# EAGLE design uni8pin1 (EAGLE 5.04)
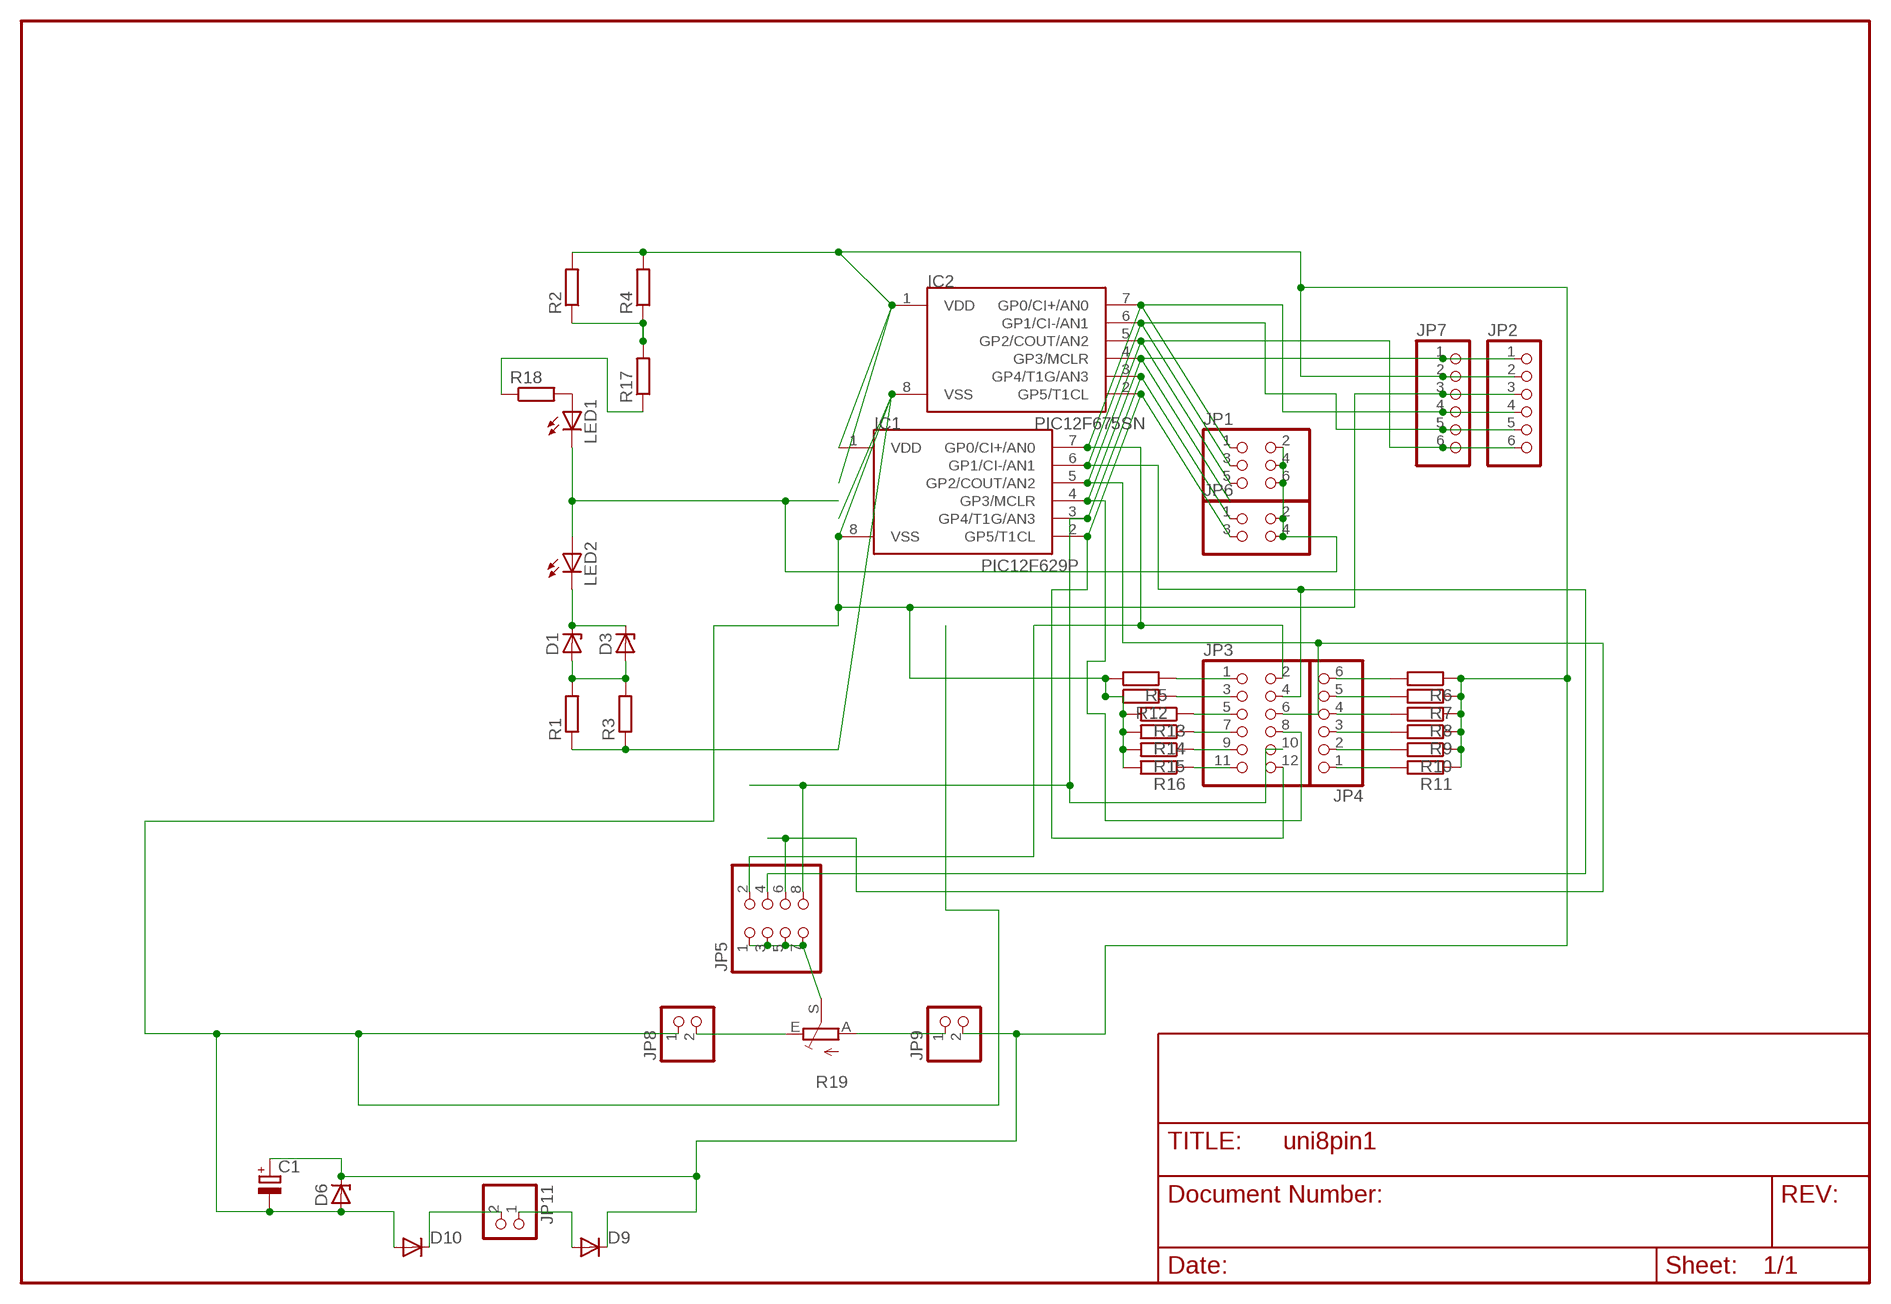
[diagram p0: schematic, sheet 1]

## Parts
C1  CPOL-EU5-13  [2,5-5-FLAT]
D1  ZENER-DIODESOT23  [SOT23]
D3  ZENER-DIODEZD-2.5  [ZDIO-2.5]
D6  ZENER-DIODEZD-2.5  [ZDIO-2.5]
D9  DIODE-D-5  [D-5]
D10  DIODE-D-5  [D-5]
IC1  PIC12F629P  [DIL8]
IC2  PIC12F675SN  [SO-08]
JP1  PINHD-2X3  [2X03]
JP2  PINHD-1X6  [1X06]
JP3  PINHD-2X6  [2X06]
JP4  PINHD-1X6  [1X06]
JP5  PINHD-2X4  [2X04]
JP6  PINHD-2X2  [2X02]
JP7  PINHD-1X6  [1X06]
JP8  PINHD-1X2  [1X02]
JP9  PINHD-1X2  [1X02]
JP11  PINHD-1X2  [1X02]
LED1  LED5MM  [LED5MM]
LED2  LED5MM  [LED5MM]
R1  R-EU_0204/2V  [0204V]
R2  R-EU_0204/2V  [0204V]
R3  R-EU_R1206  [R1206]
R4  R-EU_R1206  [R1206]
R5  R-EU_R1206  [R1206]
R6  R-EU_R1206  [R1206]
R7  R-EU_R1206  [R1206]
R8  R-EU_R1206  [R1206]
R9  R-EU_R1206  [R1206]
R10  R-EU_R1206  [R1206]
R11  R-EU_R1206  [R1206]
R12  R-EU_R1206  [R1206]
R13  R-EU_R1206  [R1206]
R14  R-EU_R1206  [R1206]
R15  R-EU_R1206  [R1206]
R16  R-EU_R1206  [R1206]
R17  R-EU_R0805  [R0805]
R18  R-EU_R0805  [R0805]
R19  TRIM_EU-CA6V  [CA6V]

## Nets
N$1: IC1.3(GP4/T1G/AN3) IC2.3(GP4/T1G/AN3) JP3.10 JP5.8 JP6.1
N$2: D1.3(C) D3.C LED2.K(C)
N$3: D1.1(A) D3.A R1.2 R3.2
N$4: JP1.2 JP1.4 JP1.6 JP6.2 JP6.4 LED1.K(C) LED2.A
N$5: C1.- D6.A D10.A IC1.8(VSS) IC2.8(VSS) JP2.3 JP7.3 JP8.1 R1.1 R3.1 R5.2 R12.2 R13.2 R14.2 R15.2 R16.2
N$6: C1.+ D6.C D9.C IC1.1(VDD) IC2.1(VDD) JP2.2 JP7.2 JP9.2 R2.2 R4.2 R6.1 R7.1 R8.1 R9.1 R10.1 R11.1
N$7: R2.1 R4.1 R17.2
N$8: R17.1 R18.1
N$9: IC1.2(GP5/T1CL) IC2.2(GP5/T1CL) JP3.12 JP6.3
N$10: LED1.A R18.2
N$11: IC1.4(GP3/MCLR) IC2.4(GP3/MCLR) JP2.1 JP3.8 JP7.1
N$12: IC1.5(GP2/COUT/AN2) IC2.5(GP2/COUT/AN2) JP1.5 JP2.6 JP3.6 JP5.6 JP7.6
N$13: IC1.6(GP1/CI-/AN1) IC2.6(GP1/CI-/AN1) JP1.3 JP2.5 JP3.4 JP5.4 JP7.5
N$14: IC1.7(GP0/CI+/AN0) IC2.7(GP0/CI+/AN0) JP1.1 JP2.4 JP3.2 JP5.2 JP7.4
N$15: JP4.6 R6.2
N$16: JP5.1 JP5.3 JP5.5 JP5.7 R19.S
N$18: JP3.1 R5.1
N$21: JP3.3 R12.1
N$22: JP3.5 R13.1
N$23: JP3.7 R14.1
N$24: JP3.9 R15.1
N$25: JP3.11 R16.1
N$26: JP4.5 R7.2
N$27: JP4.4 R8.2
N$28: JP4.3 R9.2
N$29: JP4.2 R10.2
N$30: JP4.1 R11.2
N$31: JP9.1 R19.A
N$32: JP8.2 R19.E
N$34: D10.C JP11.2
N$35: D9.A JP11.1

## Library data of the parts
C1 = rcl-2:CPOL-EU: POLARIZED CAPACITOR, European symbol
D1 D3 D6 = diode-1:ZENER-DIODE: Z-Diode
D9 D10 = diode-1:DIODE-: DIODE
IC1 IC2 = microchip-5:PIC12F6*: uPC nW 1k Program Flash memory 2x Timer Comparator 10b A/D converter/ 4xIN
JP1 = pinhead(2):PINHD-2X3: PIN HEADER
JP2 JP7 = pinhead:PINHD-1X6: PIN HEADER
JP3 = pinhead(2):PINHD-2X6: PIN HEADER
JP4 = pinhead(2):PINHD-1X6: PIN HEADER
JP5 = pinhead(2):PINHD-2X4: PIN HEADER
JP6 = pinhead(2):PINHD-2X2: PIN HEADER
JP8 JP9 JP11 = pinhead(2):PINHD-1X2: PIN HEADER
LED1 LED2 = led:LED: LED
R1-R18 = rcl-2:R-EU_: RESISTOR, European symbol
R19 = pot:TRIM_EU-: POTENTIOMETER

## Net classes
0 default: width 0.3 mm, drill 0.6 mm, clearance 0.2 mm
1 power: width 0.4 mm, drill 0.6 mm, clearance 0.2 mm

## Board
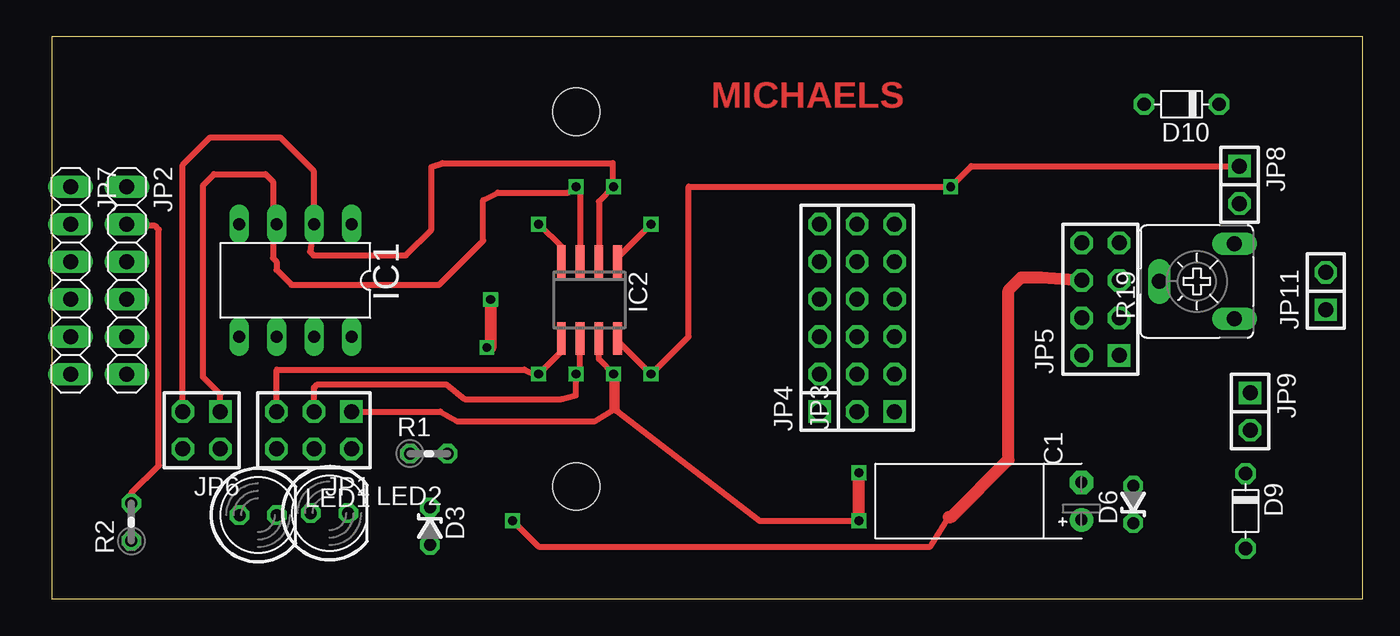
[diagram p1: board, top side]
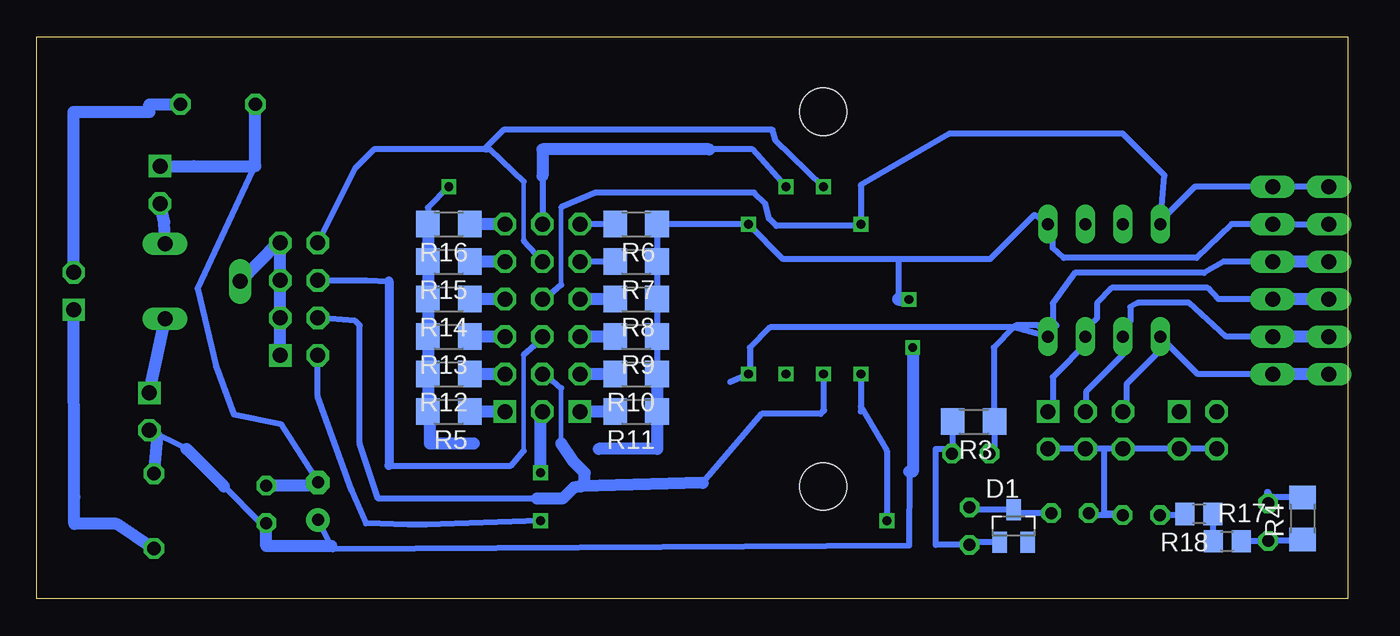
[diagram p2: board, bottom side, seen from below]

Size 88.9 x 38.1 mm. Coordinates in mm from the lower left corner, seen from the top.
Outline: 0,0 88.9,0 88.9,38.1 0,38.1 0,0
Copper layers (1*16): Top 0.035mm / dielectric 1.5mm / Bottom 0.035mm
Design rules "default": minimum track width 10mil, minimum drill 24mil, track to track 8mil, track to pad 8mil, pad to pad 8mil, via to via 8mil, smd to smd 8mil, copper to edge 40mil, drill to drill 8mil, minimum pad ring 10mil, minimum via ring 8mil, stop-mask expansion 4mil, vias tented up to drill 0mil, thermal gap 10mil
Holes 3.2 mm at 35.56,33.02 35.56,7.62

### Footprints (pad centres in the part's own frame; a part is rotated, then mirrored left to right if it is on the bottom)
2,5-5-FLAT = drill 0.813 pad 1.6 round: + -1.27,0 | drill 0.813 pad 1.6 octagon: - 1.27,0
SOT23 = smd 1 x 1.4: 1 -0.95,-1.1; 2 0.95,-1.1; 3 0,1.1
ZDIO-2.5 = drill 0.813 octagon: A 1.27,0; C -1.27,0
D-5 = drill 0.9 octagon: A 2.54,0; C -2.54,0
DIL8 = drill 0.813 long: 1 -3.81,-3.81; 2 -1.27,-3.81; 3 1.27,-3.81; 4 3.81,-3.81; 5 3.81,3.81; 6 1.27,3.81; 7 -1.27,3.81; 8 -3.81,3.81
SO-08 = smd 0.6 x 2.2: 1 -1.905,-2.6; 2 -0.635,-2.6; 3 0.635,-2.6; 4 1.905,-2.6; 5 1.905,2.6; 6 0.635,2.6; 7 -0.635,2.6; 8 -1.905,2.6
2X03 = drill 1.016 square: 1 -2.54,-1.27 | drill 1.016 octagon: 2 -2.54,1.27; 3 0,-1.27; 4 0,1.27; 5 2.54,-1.27; 6 2.54,1.27
1X06 = drill 1.016 long: 1 -6.35,0; 2 -3.81,0; 3 -1.27,0; 4 1.27,0; 5 3.81,0; 6 6.35,0
2X06 = drill 1.016 square: 1 -6.35,-1.27 | drill 1.016 octagon: 2 -6.35,1.27; 3 -3.81,-1.27; 4 -3.81,1.27; 5 -1.27,-1.27; 6 -1.27,1.27; 7 1.27,-1.27; 8 1.27,1.27; 9 3.81,-1.27; 10 3.81,1.27; 11 6.35,-1.27; 12 6.35,1.27
1X06' = drill 1.016 square: 1 -6.35,0 | drill 1.016 octagon: 2 -3.81,0; 3 -1.27,0; 4 1.27,0; 5 3.81,0; 6 6.35,0
2X04 = drill 1.016 square: 1 -3.81,-1.27 | drill 1.016 octagon: 2 -3.81,1.27; 3 -1.27,-1.27; 4 -1.27,1.27; 5 1.27,-1.27; 6 1.27,1.27; 7 3.81,-1.27; 8 3.81,1.27
2X02 = drill 1.016 square: 1 -1.27,-1.27 | drill 1.016 octagon: 2 -1.27,1.27; 3 1.27,-1.27; 4 1.27,1.27
1X02 = drill 1.016 square: 1 -1.27,0 | drill 1.016 octagon: 2 1.27,0
LED5MM = drill 0.813 octagon: A -1.27,0; K 1.27,0
0204V = drill 0.813 octagon: 1 -1.27,0; 2 1.27,0
R1206 = smd 1.6 x 1.803: 1 -1.422,0; 2 1.422,0
R0805 = smd 1.3 x 1.5: 1 -0.95,0; 2 0.95,0
CA6V = drill 1.016 long: A -2.54,-2.54; E 2.54,-2.54; S 0,2.54

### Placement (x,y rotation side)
C1  69.83,6.62 90 top
D1  22.65,4.94 0 bottom
D3  25.64,4.94 270 top
D6  73.34,6.41 90 top
D9  80.96,5.95 270 top
D10  76.62,33.53 180 top
IC1  16.51,21.59 180 top
IC2  36.46,20.26 180 top
JP1  17.78,11.43 180 top
JP2  5.08,21.59 270 top
JP3  55.88,19.05 90 top
JP4  [1X06']  52.07,19.05 90 top
JP5  71.12,20.32 90 top
JP6  10.16,11.43 180 top
JP7  1.27,21.59 270 top
JP8  80.55,28.06 270 top
JP9  81.28,12.7 270 top
JP11  86.4,20.87 90 top
LED1  13.99,5.68 0 top
LED2  18.83,5.81 0 top
R1  25.56,9.85 0 top
R2  5.39,5.2 90 top
R3  25.36,12.02 180 bottom
R4  3.06,5.46 90 bottom
R5  60.96,12.7 180 bottom
R6  48.26,25.4 180 bottom
R7  48.26,22.86 180 bottom
R8  48.26,20.32 180 bottom
R9  48.26,17.78 180 bottom
R10  48.26,15.24 180 bottom
R11  48.26,12.7 180 bottom
R12  60.96,15.24 180 bottom
R13  60.96,17.78 180 bottom
R14  60.96,20.32 180 bottom
R15  60.96,22.86 180 bottom
R16  60.96,25.4 180 bottom
R17  8.17,3.91 0 bottom
R18  10.09,5.75 180 bottom
R19  77.66,21.52 90 top

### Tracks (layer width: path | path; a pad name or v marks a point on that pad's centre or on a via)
N$1  (via drill 0.6)
  Top 0.406: JP6.1 11.43,13.86 10.25,15.04 10.25,28.04 11,28.79 14.5,28.79 15,28.29 | IC1.3 14.97,25.82 15,25.79 15,28.29 | IC2.3 35.83,27.68 v35.56,27.94 35.6,27.94 | 15,28.29 15,23.1 15.24,22.86 15.24,22.3 16.25,21.29 26.25,21.29 29.25,24.29 29.25,27.04 30.25,27.54 35,27.54 35.6,27.94 | 35.6,27.94 35.75,27.79
  Bottom 0.305: 55.88,28.29 55.88,24.29
  Bottom 0.406: JP5.8 67.31,29.21 66.04,30.48 58.5,30.48 | 58.5,30.48 58.19,30.48 55.88,28.29 | JP3.10 54.61,22.9 55.88,24.29 | v35.56,27.94 38.81,31.1 39,31.79 57.25,31.79 58.5,30.54 58.5,30.48
N$2
  Bottom 0.406: LED2.K 22.65,5.81 D1.3 25.64,6.04 D3.C
N$3
  Bottom 0.406: D1.1 25.64,3.84 D3.A 27.94,3.67 27.94,10.16 26.83,10.16 R1.2 26.79,9.85 R3.2
N$4
  Bottom 0.406: JP6.4 JP6.2 JP1.6 16.54,10.16 | JP1.2 JP1.4 16.54,10.16 | 16.54,10.16 16.54,5.79 15.26,5.79 LED1.K 17.56,5.68 LED2.A
N$5  (via drill 0.6)
  Top 0.406: IC2.8 38.37,17.52 v40.64,15.24 43.18,17.78 43.18,27.94 v60.96,27.94 62.35,29.33 JP8.1
  Bottom 0.406: JP2.3 8.43,22.86 9.75,22.1 18.5,22.1 20,20.04 20,18.79 19.75,18.54 19.88,18.41 IC1.8 | 41.89,14.7 v40.64,15.24 40.59,15.24 40.54,15.29 40.54,17.04 39.17,18.41 22.63,18.41 | 22.63,18.41 24,17.04 24,12.29 23.94,12.23 R3.1 23.94,10.35 24.29,10 R1.1 | IC1.8 22.63,18.41 | IC1.8 20.87,18.41 21,18.54 22.5,18.54 22.63,18.41 | R16.2 62.38,26.52 v60.96,27.94 | C1.- 72.37,11.87 75.54,12.5 76.75,15.75 78,21.04 74.25,29.04 74.5,29.29 78,29.29 78.04,29.33 | 78.04,29.33 78.25,29.54 | JP8.1 78.04,29.33
  Bottom 0.813: JP7.3 JP2.3 | 59.25,10.54 62.25,10.54 62.25,12.7 R5.2 R12.2 R13.2 R14.2 R15.2 R16.2 | D10.A 74.08,29.33 JP8.1 | C1.- 69.83,7.68 D6.A
N$6  (via drill 0.6)
  Top 0.406: IC2.1 38.37,23.12 v40.64,25.4 | R2.2 5.39,7.18 7.25,9.04 7.25,25.04 7,25.29 5,25.29 | 5,25.29 4.75,25.29 4.5,25.54 4.75,25.54 5,25.29 | 5,25.29 5.08,25.37 JP2.2
  Top 0.813: v29.5,17.04 29.75,17.04 v29.75,20.29
  Bottom 0.406: 30.48,23.04 24.25,23.04 21.26,26.03 IC1.1 20.05,25.99 20.25,25.79 20,25.54 20,23.79 19.25,23.11 10.25,23.11 7.89,25.4 JP2.2 JP7.2 | 30.48,23.04 38.29,23.04 v40.64,25.39 v40.64,25.4 46.64,25.4 46.75,25.29 46.84,25.38 R6.1 46.84,22.95 46.93,22.86 | C1.+ 68.94,3.57 68.83,3.35 29.75,3.6 29.73,8.62 | 30.48,23.04 30.48,20.32 | D6.C 73.72,5.14 76.2,7.62 | 78.74,10.16 JP9.2 | 46.8,15.24 46.75,15.29 | 46.8,15.24 R10.1 46.84,17.63 46.99,17.78 | 46.8,15.24 46.84,15.2 | 46.99,17.78 47,17.79 | 46.99,17.78 R9.1 R8.1 | R8.1 46.84,20.45 46.75,20.54 | 46.93,22.86 47,22.79 46.84,22.63 R8.1 | 46.93,22.86 R7.1 | R4.2 5.46,6.88 5.46,7.25 5.39,7.25 R2.2
  Bottom 0.813: 29.73,8.62 29.5,8.62 v29.5,17.04 | v29.75,20.29 30.48,20.29 30.48,20.32 | 50.8,10.16 46.84,10.16 R11.1 R10.1 | 76.2,7.62 78.74,10.16 | JP9.2 80.74,11.03 D9.C | D6.C 73.34,3.57 68.94,3.57
N$7
  Bottom 0.406: R17.2 5.39,3.91 R2.1 3.06,3.93 R4.1
N$8
  Bottom 0.406: R18.1 9.12,5.75 R17.1
N$9  (via drill 0.6)
  Top 0.406: IC2.2 37.09,26.93 v38.1,27.94 38.1,27.98 38.04,28.04 38.04,29.54 26.5,29.54 25.75,29.29 25.75,25.04 24,23.29 17.75,23.29 17.51,23.53 IC1.2 17.51,25.8 | JP6.3 8.89,29.43 10.75,31.29 15.5,31.29 17.75,29.04 17.75,26.54 18,26.29 17.51,25.8 | 17.51,25.8 17.5,25.79
  Bottom 0.406: v38.1,27.94 40.35,30.48 43.31,30.48 | 54.61,28.68 JP3.12
  Bottom 0.813: 43.31,30.48 54.61,30.48 54.61,28.68
N$10
  Bottom 0.406: LED1.A 11.04,5.68 R18.2
N$11  (via drill 0.6)
  Top 0.406: IC2.4 34.55,23.86 v33.02,25.4
  Bottom 0.305: 53.34,26.54 53.34,21.29
  Bottom 0.406: 12.43,25.86 12.5,25.79 | 12.43,25.86 IC1.4 12.43,28.72 15.25,31.54 27,31.54 33.04,28.04 33.02,28.02 v33.02,25.4 32.86,25.4 32.75,25.29 38.75,25.29 39.25,25.79 39.5,26.79 40.25,27.54 51,27.54 53.34,26.54 | 12.43,25.86 10.35,27.94 JP2.1 JP7.1 | JP3.8 54.47,20.32 53.34,21.29
N$12  (via drill 0.6)
  Top 0.406: IC2.5 34.55,16.77 v33.02,15.24 33.02,15.06 | v15.25,12.54 15.25,15.54 32.04,15.54 33.02,15.06 | 33.02,15.06 33.04,15.04 | 60.83,5.54 59.58,3.54 33,3.54 v31.25,5.29
  Top 0.813: 60.83,5.54 61,5.54 64.88,9.41 64.88,20.91 65.75,21.79 67.11,21.79 JP5.6
  Bottom 0.305: 55.88,10.04 55.88,16.54
  Bottom 0.406: JP2.6 10.16,15.24 IC1.5 12.43,17.11 15,14.54 15,12.79 v15.24,12.55 | v33.02,15.24 33.02,13.04 | 33.02,13.04 33.02,12.7 | v15.24,12.55 v15.25,12.54 | v15.24,12.55 JP1.5 | JP5.6 66.55,21.59 65.02,21.54 | 65.02,9.04 56.75,9.04 55.88,10.04 | 33.02,13.04 31.25,10.04 v31.25,5.29 | JP3.6 54.61,17.68 55.88,16.54
  Bottom 0.61: 65.02,21.54 65.02,9.04
  Bottom 0.813: JP7.6 JP2.6
N$13  (via drill 0.6)
  Top 0.406: IC2.6 35.83,15.51 v35.56,15.24 35.59,15.24 35.79,15.04 35.54,14.79 35.54,13.79 34.54,13.54 28,13.54 26.75,14.54 18,14.54 17.78,14.32 JP1.3
  Bottom 0.305: 53.34,10.54 53.34,14.29
  Bottom 0.406: JP2.5 8.24,17.78 10.75,20.07 14.25,20.07 14.75,19.79 14.75,18.79 15.13,18.41 | 15.13,18.41 15.25,18.29 15.25,16.54 17.75,14.04 17.75,12.54 17.78,12.57 JP1.3 | 15.13,18.41 IC1.6 | v35.56,15.24 35.56,12.79 | 35.56,12.79 35.56,12.7 | 54.61,14.9 JP3.4 54.55,15.24 54.5,15.29 53.34,14.29 | JP5.4 67.31,18.85 67,18.54 67,10.54 65.75,6.79 55,6.79 | 43.75,7.87 39.75,12.54 35.75,12.54 35.5,12.79 35.56,12.79
  Bottom 0.813: JP7.5 JP2.5 | 43.75,7.87 52,7.62 | 52,7.62 52.5,7.54 53.25,6.79 55,6.79 | 53.34,10.54 52.5,9.29 51.75,8.54 51.75,7.79 52,7.62
N$14  (via drill 0.6)
  Top 0.406: IC2.7 37.09,16.25 v38.1,15.24 v38.1,15.23 38.29,15.04 | JP1.1 26.34,12.7 27.5,12.04 36.79,12.04 38.04,12.79 38.04,14.79 38.29,15.04 | 38.29,15.04 38.29,12.75 48,5.29 v54.75,5.29
  Top 0.813: v54.75,5.29 v54.75,8.54
  Bottom 0.406: JP2.4 8.78,20.32 9.5,21.08 16,21.08 17,20.04 17,19.04 17.51,18.53 IC1.7 17.51,17.53 20,15.04 20,13.04 20.32,12.72 JP1.1 | JP5.2 69.85,13.72 67.54,7.37 66.58,5.12 63.75,5.04 62.5,5.04 v54.75,5.29
  Bottom 0.813: JP7.4 JP2.4 | v54.75,8.54 54.75,12.56 JP3.2
N$15
  Bottom 0.406: R6.2 49.68,25.36 49.75,25.29 49.86,25.4 JP4.6
N$16
  Bottom 0.813: R19.S 72.58,24.13 JP5.7 JP5.5 JP5.3 JP5.1
N$18
  Bottom 0.813: JP3.1 R5.1
N$21
  Bottom 0.813: JP3.3 R12.1
N$22
  Bottom 0.813: JP3.5 R13.1
N$23
  Bottom 0.813: JP3.7 R14.1
N$24
  Bottom 0.813: JP3.9 R15.1
N$25
  Bottom 0.813: JP3.11 R16.1
N$26
  Bottom 0.406: R7.2 49.93,22.86 50,22.79 50.07,22.86 JP4.5
N$27
  Bottom 0.813: R8.2 JP4.4
N$28
  Bottom 0.813: R9.2 JP4.3
N$29
  Bottom 0.813: R10.2 JP4.2
N$30
  Bottom 0.813: R11.2 JP4.1
N$31
  Bottom 0.813: JP9.1 80.74,16.44 R19.A
N$32
  Bottom 0.813: JP8.2 80.26,25.56 R19.E
N$34
  Bottom 0.813: JP11.2 86.4,33.02 81.28,33.02 81.28,33.53 D10.C
N$35
  Bottom 0.813: D9.A 83.5,5.08 86.36,5.08 86.36,6.9 JP11.1

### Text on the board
Top: MICHAELS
